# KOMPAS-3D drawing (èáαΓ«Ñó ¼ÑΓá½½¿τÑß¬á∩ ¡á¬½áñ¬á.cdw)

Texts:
  Стропильная нога
  картоев
  Noncommercial version
  Гвозди
  Стропильная
  нога 60х140
  стропиьные ноги 60х140
  накладки 40х120
  ГАПОУ ПСЭК им. П.Мачнева
Dimensions and other numbers on the sheet: 80; 5,54; 120; 440; 90; 30; 60; 140; 22; 40; 1:1; 1; 0; 2; 3; 4; 5; 6; 7; 8; 9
